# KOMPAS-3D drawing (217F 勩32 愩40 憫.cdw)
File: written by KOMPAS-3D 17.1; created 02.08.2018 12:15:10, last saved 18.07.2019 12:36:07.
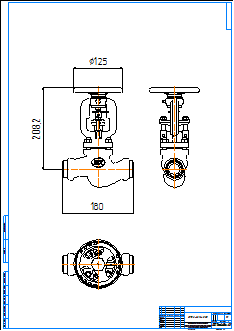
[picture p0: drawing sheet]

Sheet 1: A1, portrait

Title block, sheet 1: name: 217F Ду32 Ру40 СС; material: Внимание! Данный продукт является объектом авторского права ООО «Торговый Дом АДЛ». / Запрещается изменение, копирование, распространение / (в том числе путем копирования на другие сайты и ресурсы в Интернете) / или любое иное использование информации и объектов без предварительного / согласия правообладателя (ООО «Торговый Дом АДЛ»).; sheets: 1; organisation: ООО "Торговый дом АДЛ"; sheet format: A1; stored path: \\adlc.lan\data\АДЛ_ПКД\3D-модели\Поставщики\Zetkama\Вентили\217F\KOMPAS 2D\217F Ду32 Ру40 СС.cdw

Views: Вид 1, Проекционный вид 2, Проекционный вид 3
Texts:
  kka
  adl
Dimensions and other numbers on the sheet: 180; 208,2; 125; 1:1; 1; 217F Ду32 Ру40 СС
